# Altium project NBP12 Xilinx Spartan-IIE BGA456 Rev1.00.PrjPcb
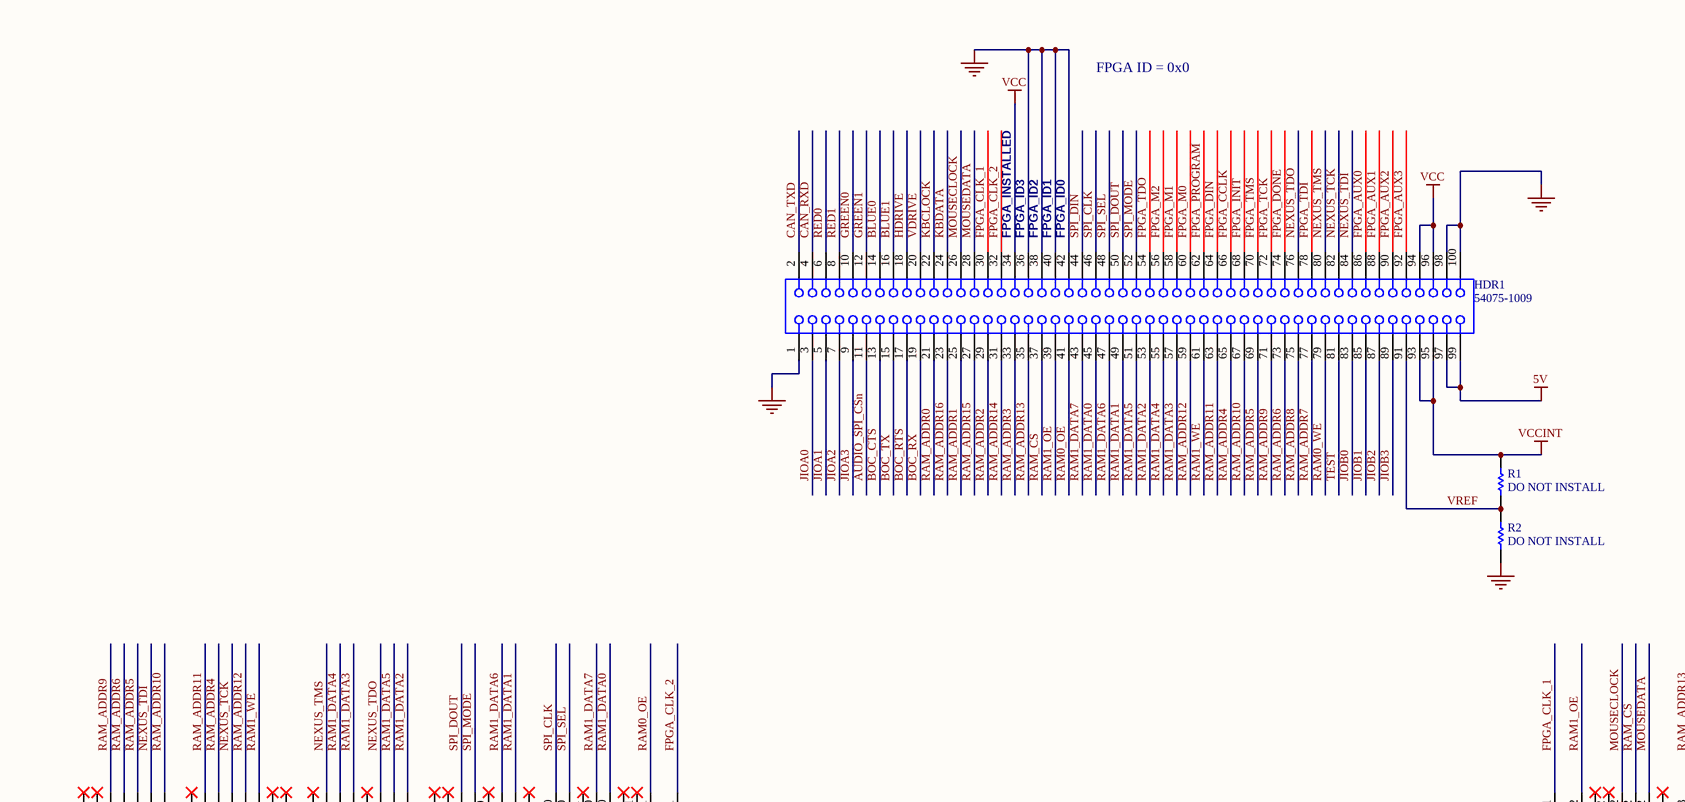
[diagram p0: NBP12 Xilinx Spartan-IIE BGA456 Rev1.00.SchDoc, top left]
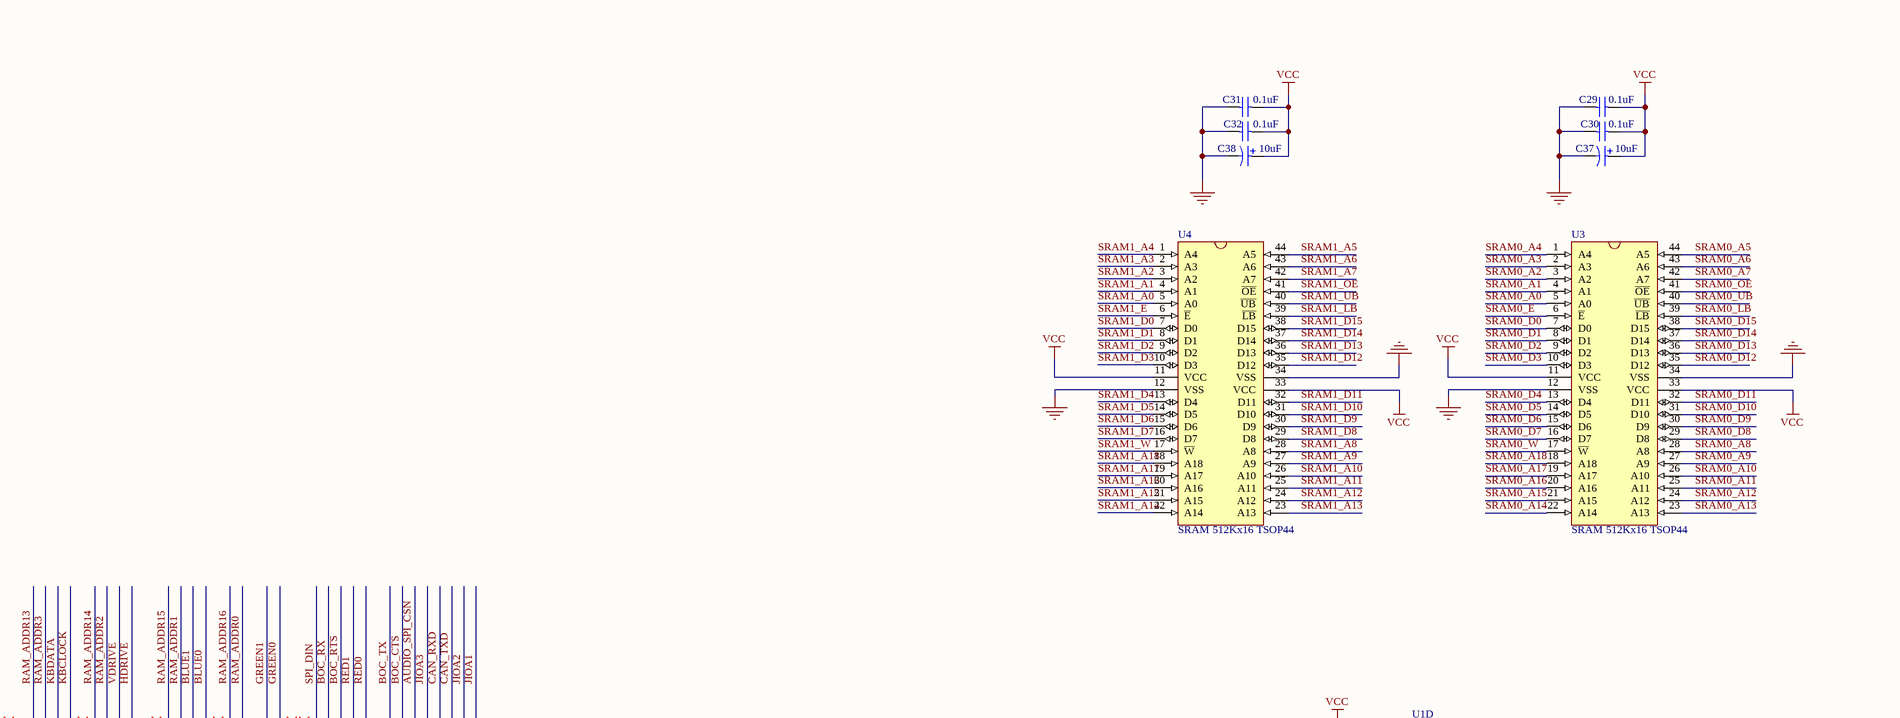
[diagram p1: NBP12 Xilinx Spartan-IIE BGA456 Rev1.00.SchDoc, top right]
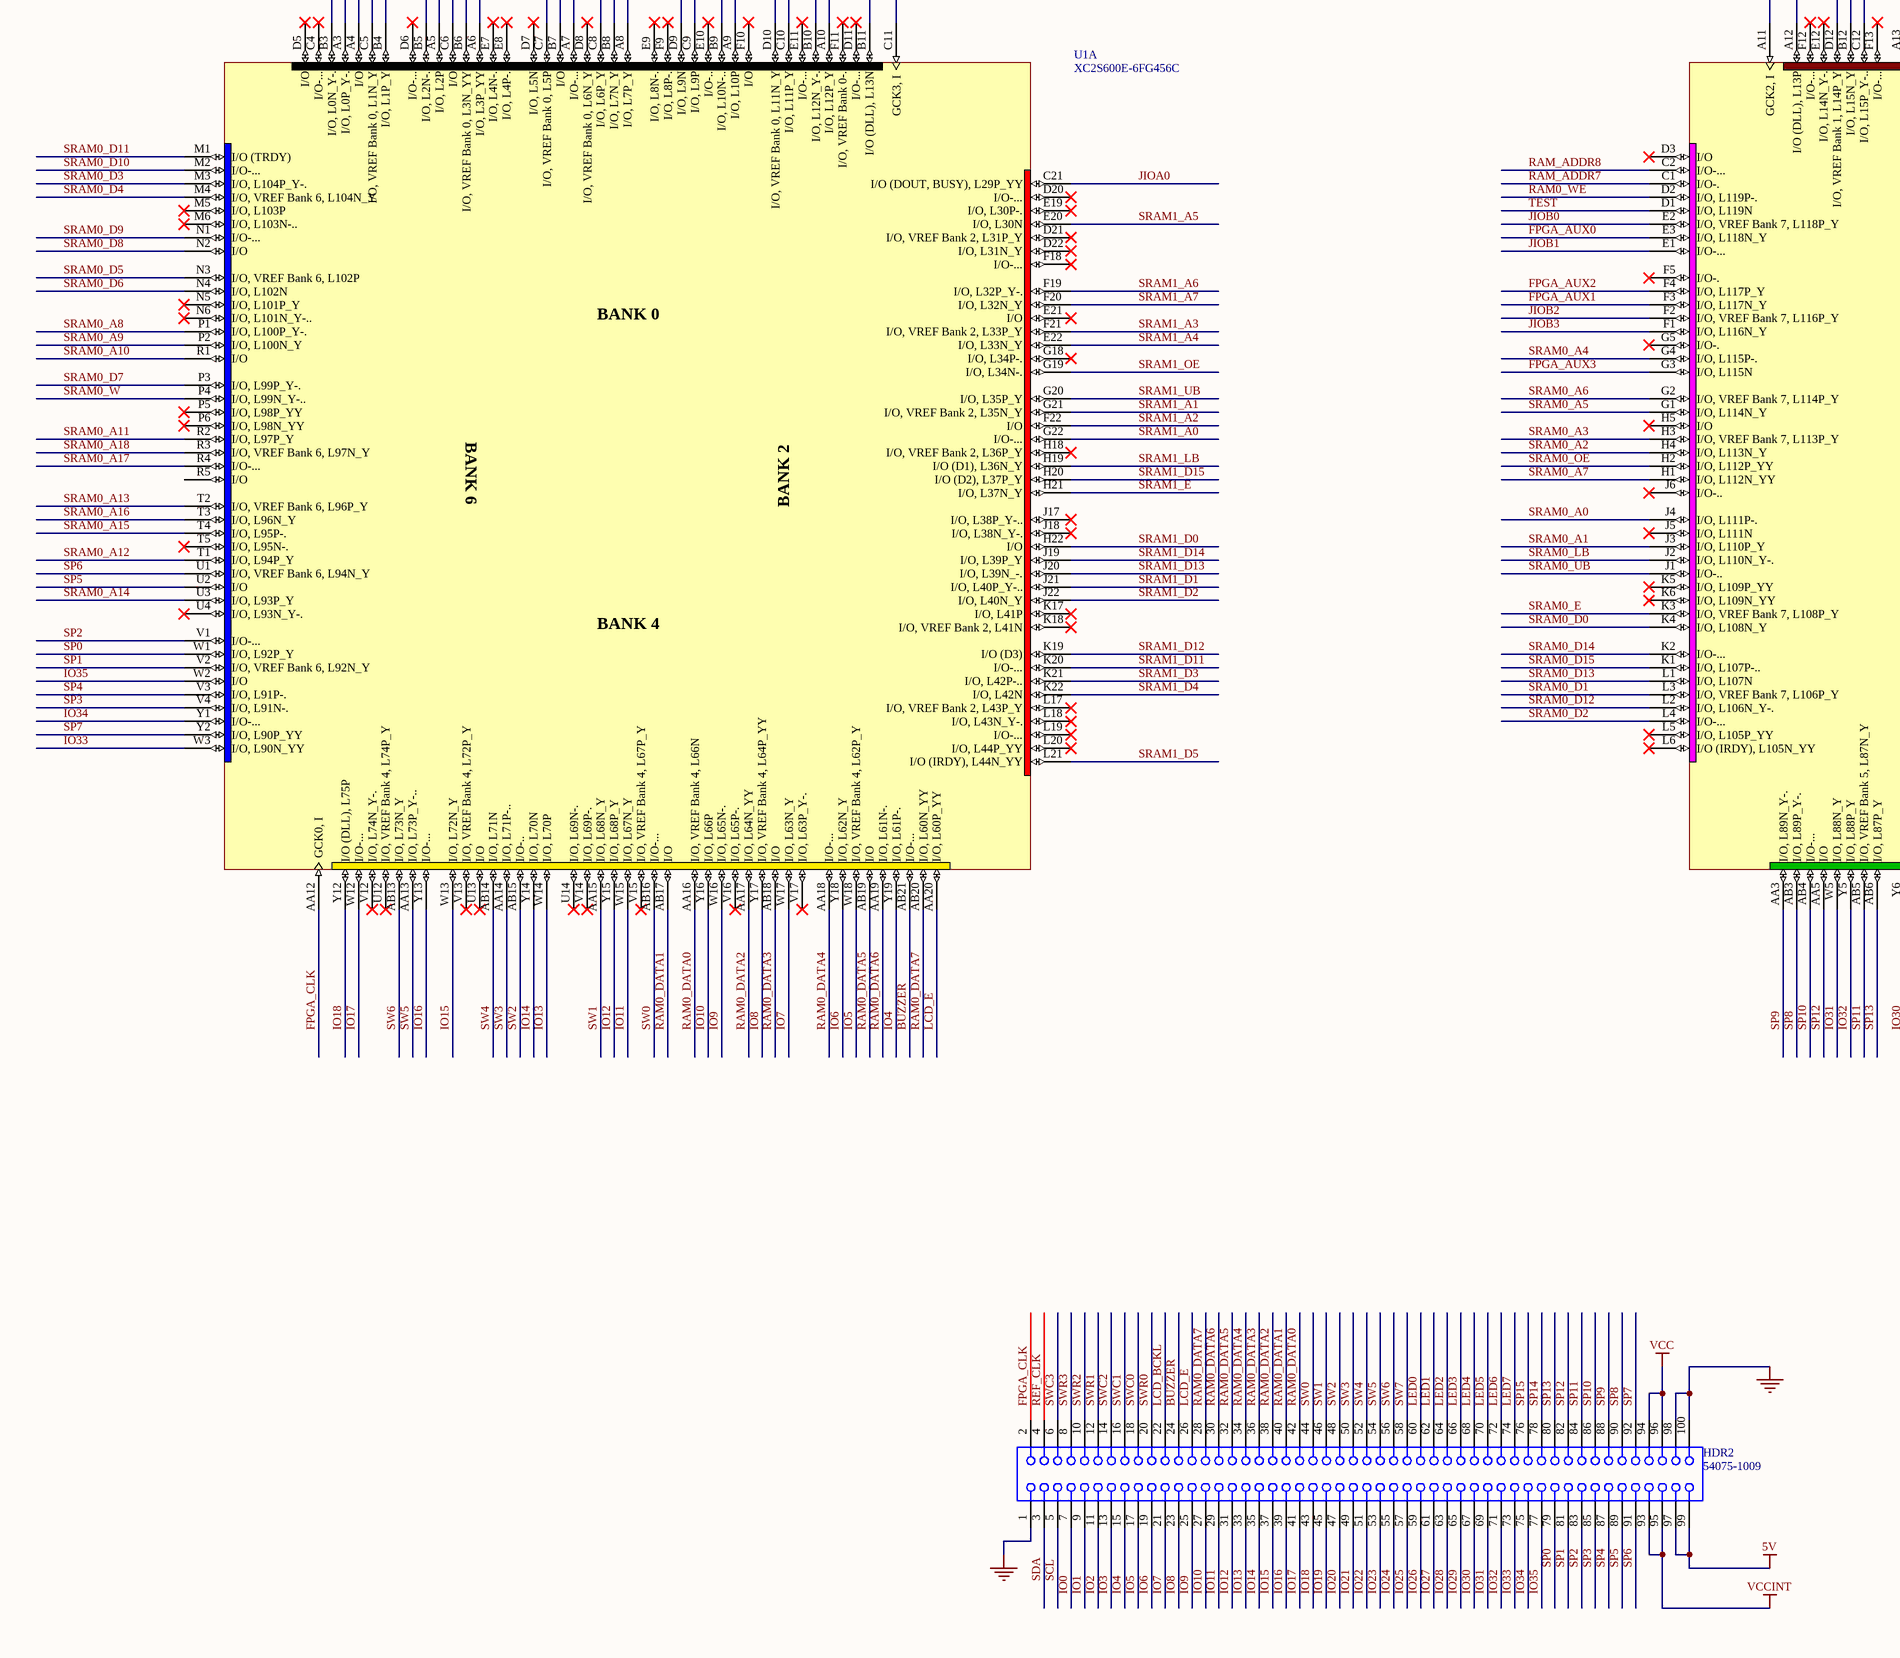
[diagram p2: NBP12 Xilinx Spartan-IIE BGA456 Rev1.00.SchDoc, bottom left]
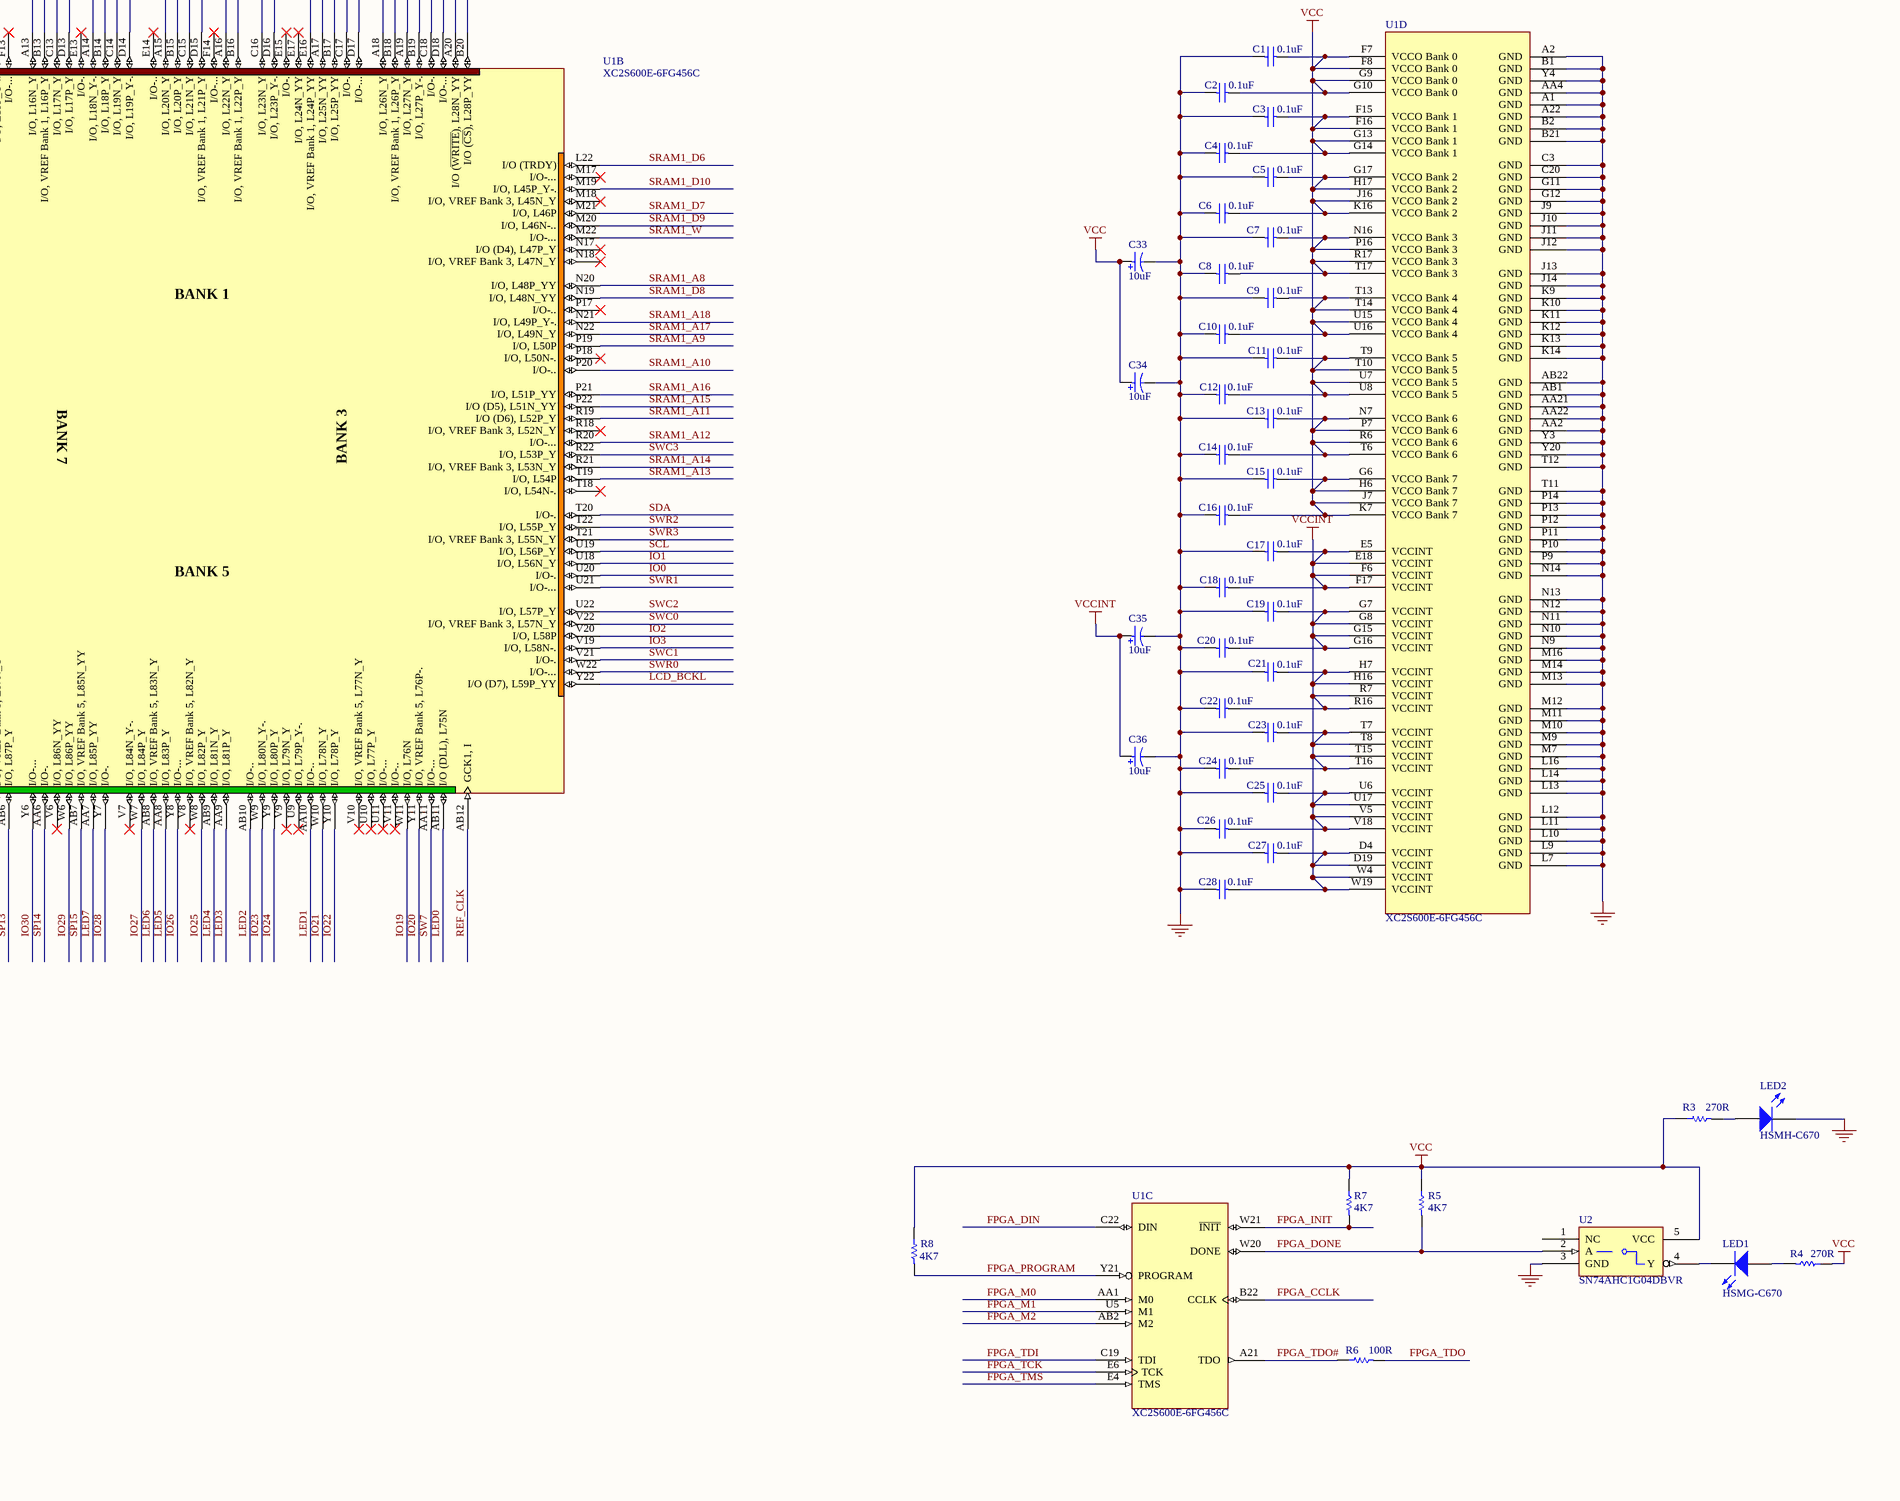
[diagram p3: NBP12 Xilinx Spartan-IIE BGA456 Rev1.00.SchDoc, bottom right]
1 sheet, 54 parts. Net scope: global (net labels, ports and power ports of the same name join across sheets).
Board file: NBP12 Xilinx Spartan-IIE BGA456 Rev1.00.PcbDoc

## Sheet NBP12 Xilinx Spartan-IIE BGA456 Rev1.00.SchDoc
size D; Organization: Altium Limited; Address1: L3, 12a Rodborough Rd; Address2: Frenchs Forest; Address3: NSW; Address4: Australia 2086; DocumentNumber: 1; SheetNumber: 1; SheetTotal: 1

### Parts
C1  0.1uF  [CC1608-0603]
C2  0.1uF  [CC1608-0603]
C3  0.1uF  [CC1608-0603]
C4  0.1uF  [CC1608-0603]
C5  0.1uF  [CC1608-0603]
C6  0.1uF  [CC1608-0603]
C7  0.1uF  [CC1608-0603]
C8  0.1uF  [CC1608-0603]
C9  0.1uF  [CC1608-0603]
C10  0.1uF  [CC1608-0603]
C11  0.1uF  [CC1608-0603]
C12  0.1uF  [CC1608-0603]
C13  0.1uF  [CC1608-0603]
C14  0.1uF  [CC1608-0603]
C15  0.1uF  [CC1608-0603]
C16  0.1uF  [CC1608-0603]
C17  0.1uF  [CC1608-0603]
C18  0.1uF  [CC1608-0603]
C19  0.1uF  [CC1608-0603]
C20  0.1uF  [CC1608-0603]
C21  0.1uF  [CC1608-0603]
C22  0.1uF  [CC1608-0603]
C23  0.1uF  [CC1608-0603]
C24  0.1uF  [CC1608-0603]
C25  0.1uF  [CC1608-0603]
C26  0.1uF  [CC1608-0603]
C27  0.1uF  [CC1608-0603]
C28  0.1uF  [CC1608-0603]
C29  0.1uF  [CC1608-0603]
C30  0.1uF  [CC1608-0603]
C31  0.1uF  [CC1608-0603]
C32  0.1uF  [CC1608-0603]
C33  10uF  [MCCT-B]
C34  10uF  [MCCT-B]
C35  10uF  [MCCT-B]
C36  10uF  [MCCT-B]
C37  10uF  [MCCT-B]
C38  10uF  [MCCT-B]
HDR1  54075-1009  [54075]
HDR2  54075-1009  [54075]
LED1  HSMG-C670  [SMD _LED]
LED2  HSMH-C670  [SMD _LED]
R1  DO NOT INSTALL  [CC2012-0805]
R2  DO NOT INSTALL  [CC2012-0805]
R3  270R  [CC2012-0805]
R4  270R  [CC2012-0805]
R5  4K7  [CC2012-0805]
R6  100R  [CC2012-0805]
R7  4K7  [CC2012-0805]
R8  4K7  [CC2012-0805]
U1  XC2S600E-6FG456C  [FG456]  (parts A,B,C,D of 4)
U2  SN74AHC1G04DBVR  [SO-G5/P.95]
U3  SRAM 512Kx16 TSOP44  [SO-G44/P.8]
U4  SRAM 512Kx16 TSOP44  [SO-G44/P.8]

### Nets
5V: HDR1.97 HDR1.99 HDR2.97 HDR2.99
GND: C1.1 C2.1 C3.1 C4.1 C5.1 C6.1 C7.1 C8.1 C9.1 C10.1 C11.1 C12.1 C13.1 C14.1 C15.1 C16.1 C17.1 C18.1 C19.1 C20.1 C21.1 C22.1 C23.1 C24.1 C25.1 C26.1 C27.1 C28.1 C29.1 C30.1 C31.1 C32.1 C33.2 C34.2 C35.2 C36.2 C37.2 C38.2 HDR1.1 HDR1.36 HDR1.38 HDR1.40 HDR1.42 HDR1.98 HDR1.100 HDR2.1 HDR2.98 HDR2.100 LED2.2(K) R2.2 U1.A1(GND) U1.A2(GND) U1.A22(GND) U1.AA2(GND) U1.AA4(GND) U1.AA21(GND) U1.AA22(GND) U1.AB1(GND) U1.AB22(GND) U1.B1(GND) U1.B2(GND) U1.B21(GND) U1.C3(GND) U1.C20(GND) U1.G11(GND) U1.G12(GND) U1.J9(GND) U1.J10(GND) U1.J11(GND) U1.J12(GND) U1.J13(GND) U1.J14(GND) U1.K9(GND) U1.K10(GND) U1.K11(GND) U1.K12(GND) U1.K13(GND) U1.K14(GND) U1.L7(GND) U1.L9(GND) U1.L10(GND) U1.L11(GND) U1.L12(GND) U1.L13(GND) U1.L14(GND) U1.L16(GND) U1.M7(GND) U1.M9(GND) U1.M10(GND) U1.M11(GND) U1.M12(GND) U1.M13(GND) U1.M14(GND) U1.M16(GND) U1.N9(GND) U1.N10(GND) U1.N11(GND) U1.N12(GND) U1.N13(GND) U1.N14(GND) U1.P9(GND) U1.P10(GND) U1.P11(GND) U1.P12(GND) U1.P13(GND) U1.P14(GND) U1.T11(GND) U1.T12(GND) U1.Y3(GND) U1.Y4(GND) U1.Y20(GND) U2.3(GND) U3.12(VSS) U3.34(VSS) U4.12(VSS) U4.34(VSS)
VCC: C1.2 C2.2 C3.2 C4.2 C5.2 C6.2 C7.2 C8.2 C9.2 C10.2 C11.2 C12.2 C13.2 C14.2 C15.2 C16.2 C29.2 C30.2 C31.2 C32.2 C33.1 C34.1 C37.1 C38.1 HDR1.34 HDR1.94 HDR1.96 HDR2.94 HDR2.96 R3.1 R4.1 R5.1 R7.1 R8.1 U1.F7(VCCO_Bank_0) U1.F8(VCCO_Bank_0) U1.F15(VCCO_Bank_1) U1.F16(VCCO_Bank_1) U1.G6(VCCO_Bank_7) U1.G9(VCCO_Bank_0) U1.G10(VCCO_Bank_0) U1.G13(VCCO_Bank_1) U1.G14(VCCO_Bank_1) U1.G17(VCCO_Bank_2) U1.H6(VCCO_Bank_7) U1.H17(VCCO_Bank_2) U1.J7(VCCO_Bank_7) U1.J16(VCCO_Bank_2) U1.K7(VCCO_Bank_7) U1.K16(VCCO_Bank_2) U1.N7(VCCO_Bank_6) U1.N16(VCCO_Bank_3) U1.P7(VCCO_Bank_6) U1.P16(VCCO_Bank_3) U1.R6(VCCO_Bank_6) U1.R17(VCCO_Bank_3) U1.T6(VCCO_Bank_6) U1.T9(VCCO_Bank_5) U1.T10(VCCO_Bank_5) U1.T13(VCCO_Bank_4) U1.T14(VCCO_Bank_4) U1.T17(VCCO_Bank_3) U1.U7(VCCO_Bank_5) U1.U8(VCCO_Bank_5) U1.U15(VCCO_Bank_4) U1.U16(VCCO_Bank_4) U2.5(VCC) U3.11(VCC) U3.33(VCC) U4.11(VCC) U4.33(VCC)
VCCINT: C17.2 C18.2 C19.2 C20.2 C21.2 C22.2 C23.2 C24.2 C25.2 C26.2 C27.2 C28.2 C35.1 C36.1 HDR1.93 HDR1.95 HDR2.93 HDR2.95 R1.1 U1.D4(VCCINT) U1.D19(VCCINT) U1.E5(VCCINT) U1.E18(VCCINT) U1.F6(VCCINT) U1.F17(VCCINT) U1.G7(VCCINT) U1.G8(VCCINT) U1.G15(VCCINT) U1.G16(VCCINT) U1.H7(VCCINT) U1.H16(VCCINT) U1.R7(VCCINT) U1.R16(VCCINT) U1.T7(VCCINT) U1.T8(VCCINT) U1.T15(VCCINT) U1.T16(VCCINT) U1.U6(VCCINT) U1.U17(VCCINT) U1.V5(VCCINT) U1.V18(VCCINT) U1.W4(VCCINT) U1.W19(VCCINT)
AUDIO_SPI_CSn: HDR1.11 U1.A19(I/O,_L27N_Y)
BLUE0: HDR1.14 U1.D15(I/O,_VREF_Bank_1,_L21P_Y)
BLUE1: HDR1.16 U1.C15(I/O,_L21N_Y)
BOC_CTS: HDR1.13 U1.B18(I/O,_VREF_Bank_1,_L26P_Y)
BOC_RTS: HDR1.17 U1.B17(I/O,_L25P_YY)
BOC_RX: HDR1.19 U1.A17(I/O,_L25N_YY)
BOC_TX: HDR1.15 U1.A18(I/O,_L26N_Y)
BUZZER: HDR2.24 U1.AB21(I/O-...)
CAN_RXD: HDR1.4 U1.C18(I/O-.)
CAN_TXD: HDR1.2 U1.D18(I/O-...)
FPGA_AUX0: HDR1.86 U1.E3(I/O,_L118N_Y)
FPGA_AUX1: HDR1.88 U1.F3(I/O,_L117N_Y)
FPGA_AUX2: HDR1.90 U1.F4(I/O,_L117P_Y)
FPGA_AUX3: HDR1.92 U1.G3(I/O,_L115N)
FPGA_CCLK: HDR1.66 U1.B22(CCLK)
FPGA_CLK: HDR2.2 U1.AA12(GCK0,_I)
FPGA_CLK_1: HDR1.30 U1.A11(GCK2,_I)
FPGA_CLK_2: HDR1.32 U1.C11(GCK3,_I)
FPGA_DIN: HDR1.64 U1.C22(DIN)
FPGA_DONE: HDR1.74 R5.2 U1.W20(DONE) U2.2(A)
FPGA_INIT: HDR1.68 R7.2 U1.W21(~{INIT})
FPGA_M0: HDR1.60 U1.AA1(M0)
FPGA_M1: HDR1.58 U1.U5(M1)
FPGA_M2: HDR1.56 U1.AB2(M2)
FPGA_PROGRAM: HDR1.62 R8.2 U1.Y21(PROGRAM)
FPGA_TCK: HDR1.72 U1.E6(TCK)
FPGA_TDI: HDR1.78 U1.C19(TDI)
FPGA_TDO: HDR1.54 R6.2
FPGA_TDO#: R6.1 U1.A21(TDO)
FPGA_TMS: HDR1.70 U1.E4(TMS)
GREEN0: HDR1.10 U1.D16(I/O,_L23P_Y-.)
GREEN1: HDR1.12 U1.C16(I/O,_L23N_Y)
HDRIVE: HDR1.18 U1.D14(I/O,_L19P_Y-.)
IO0: HDR2.7 U1.U20(I/O-.)
IO1: HDR2.9 U1.U18(I/O,_L56N_Y)
IO2: HDR2.11 U1.V20(I/O,_L58P)
IO3: HDR2.13 U1.V19(I/O,_L58N-.)
IO4: HDR2.15 U1.Y19(I/O,_L61P-.)
IO5: HDR2.17 U1.W18(I/O,_VREF_Bank_4,_L62P_Y)
IO6: HDR2.19 U1.Y18(I/O,_L62N_Y)
IO7: HDR2.21 U1.W17(I/O,_L63N_Y)
IO8: HDR2.23 U1.Y17(I/O,_VREF_Bank_4,_L64P_YY)
IO9: HDR2.25 U1.W16(I/O,_L65N-.)
IO10: HDR2.27 U1.Y16(I/O,_L66P)
IO11: HDR2.29 U1.W15(I/O,_L67N_Y)
IO12: HDR2.31 U1.Y15(I/O,_L68P_Y)
IO13: HDR2.33 U1.W14(I/O,_L70P)
IO14: HDR2.35 U1.Y14(I/O,_L70N)
IO15: HDR2.37 U1.W13(I/O,_L72N_Y)
IO16: HDR2.39 U1.Y13(I/O-...)
IO17: HDR2.41 U1.W12(I/O-...)
IO18: HDR2.43 U1.Y12(I/O_(DLL),_L75P)
IO19: HDR2.45 U1.W11(I/O,_L76N)
IO20: HDR2.47 U1.Y11(I/O,_VREF_Bank_5,_L76P-.)
IO21: HDR2.49 U1.W10(I/O,_L78N_Y)
IO22: HDR2.51 U1.Y10(I/O,_L78P_Y)
IO23: HDR2.53 U1.W9(I/O,_L80N_Y-.)
IO24: HDR2.55 U1.Y9(I/O,_L80P_Y)
IO25: HDR2.57 U1.W8(I/O,_L82P_Y)
IO26: HDR2.59 U1.Y8(I/O-...)
IO27: HDR2.61 U1.W7(I/O,_L84P_Y)
IO28: HDR2.63 U1.Y7(I/O-.)
IO29: HDR2.65 U1.W6(I/O,_L86P_YY)
IO30: HDR2.67 U1.Y6(I/O-...)
IO31: HDR2.69 U1.W5(I/O,_L88N_Y)
IO32: HDR2.71 U1.Y5(I/O,_L88P_Y)
IO33: HDR2.73 U1.W3(I/O,_L90N_YY)
IO34: HDR2.75 U1.Y1(I/O-...)
IO35: HDR2.77 U1.W2(I/O)
JIOA0: HDR1.3 U1.C21(I/O_(DOUT,_BUSY),_L29P_YY)
JIOA1: HDR1.5 U1.B20(I/O_(~{CS}),_L28P_YY)
JIOA2: HDR1.7 U1.A20(I/O_(~{WRITE}),_L28N_YY)
JIOA3: HDR1.9 U1.B19(I/O,_L27P_Y-.)
JIOB0: HDR1.83 U1.E2(I/O,_VREF_Bank_7,_L118P_Y)
JIOB1: HDR1.85 U1.E1(I/O-...)
JIOB2: HDR1.87 U1.F2(I/O,_VREF_Bank_7,_L116P_Y)
JIOB3: HDR1.89 U1.F1(I/O,_L116N_Y)
KBCLOCK: HDR1.22 U1.D13(I/O,_L17P_Y)
KBDATA: HDR1.24 U1.C13(I/O,_L17N_Y)
LCD_BCKL: HDR2.22 U1.Y22(I/O_(D7),_L59P_YY)
LCD_E: HDR2.26 U1.AA20(I/O,_L60P_YY)
LED0: HDR2.60 U1.AB11(I/O_(DLL),_L75N)
LED1: HDR2.62 U1.AA10(I/O-..)
LED2: HDR2.64 U1.AB10(I/O-..)
LED3: HDR2.66 U1.AA9(I/O,_L81P_Y)
LED4: HDR2.68 U1.AB9(I/O,_L81N_Y)
LED5: HDR2.70 U1.AA8(I/O,_L83P_Y)
LED6: HDR2.72 U1.AB8(I/O,_VREF_Bank_5,_L83N_Y)
LED7: HDR2.74 U1.AA7(I/O,_L85P_YY)
MOUSECLOCK: HDR1.26 U1.D12(I/O,_VREF_Bank_1,_L14P_Y)
MOUSEDATA: HDR1.28 U1.C12(I/O,_L15P_Y-..)
NEXUS_TCK: HDR1.82 U1.C6(I/O)
NEXUS_TDI: HDR1.84 U1.C5(I/O,_VREF_Bank_0,_L1N_Y)
NEXUS_TDO: HDR1.76 U1.C8(I/O,_L6P_Y)
NEXUS_TMS: HDR1.80 U1.C7(I/O,_VREF_Bank_0,_L5P)
RAM0_DATA0: HDR2.42 U1.AA16(I/O,_VREF_Bank_4,_L66N)
RAM0_DATA1: HDR2.40 U1.AB17(I/O)
RAM0_DATA2: HDR2.38 U1.AA17(I/O,_L64N_YY)
RAM0_DATA3: HDR2.36 U1.AB18(I/O)
RAM0_DATA4: HDR2.34 U1.AA18(I/O-...)
RAM0_DATA5: HDR2.32 U1.AB19(I/O)
RAM0_DATA6: HDR2.30 U1.AA19(I/O,_L61N-.)
RAM0_DATA7: HDR2.28 U1.AB20(I/O,_L60N_YY)
RAM0_OE: HDR1.41 U1.B11(I/O_(DLL),_L13N)
RAM0_WE: HDR1.79 U1.D2(I/O,_L119P-.)
RAM1_DATA0: HDR1.45 U1.A10(I/O,_L12P_Y)
RAM1_DATA1: HDR1.49 U1.A9(I/O,_L10P)
RAM1_DATA2: HDR1.53 U1.A8(I/O,_L7P_Y)
RAM1_DATA3: HDR1.57 U1.A7(I/O-...)
RAM1_DATA4: HDR1.55 U1.B7(I/O)
RAM1_DATA5: HDR1.51 U1.B8(I/O,_L7N_Y)
RAM1_DATA6: HDR1.47 U1.B9(I/O,_L10N-..)
RAM1_DATA7: HDR1.43 U1.B10(I/O,_L12N_Y-.)
RAM1_OE: HDR1.39 U1.A12(I/O_(DLL),_L13P)
RAM1_WE: HDR1.61 U1.A6(I/O,_L3P_YY)
RAM_ADDR0: HDR1.21 U1.B16(I/O,_VREF_Bank_1,_L22P_Y)
RAM_ADDR1: HDR1.25 U1.B15(I/O,_L20P_Y)
RAM_ADDR2: HDR1.29 U1.B14(I/O,_L18P_Y)
RAM_ADDR3: HDR1.33 U1.B13(I/O,_VREF_Bank_1,_L16P_Y)
RAM_ADDR4: HDR1.65 U1.A5(I/O,_L2P)
RAM_ADDR5: HDR1.69 U1.A4(I/O)
RAM_ADDR6: HDR1.73 U1.A3(I/O,_L0P_Y-.)
RAM_ADDR7: HDR1.77 U1.C1(I/O-.)
RAM_ADDR8: HDR1.75 U1.C2(I/O-...)
RAM_ADDR9: HDR1.71 U1.B3(I/O,_L0N_Y-.)
RAM_ADDR10: HDR1.67 U1.B4(I/O,_L1P_Y)
RAM_ADDR11: HDR1.63 U1.B5(I/O,_L2N-.)
RAM_ADDR12: HDR1.59 U1.B6(I/O,_VREF_Bank_0,_L3N_YY)
RAM_ADDR13: HDR1.35 U1.A13(I/O,_L16N_Y)
RAM_ADDR14: HDR1.31 U1.A14(I/O,_L18N_Y-.)
RAM_ADDR15: HDR1.27 U1.A15(I/O,_L20N_Y)
RAM_ADDR16: HDR1.23 U1.A16(I/O,_L22N_Y)
RAM_CS: HDR1.37 U1.B12(I/O,_L15N_Y)
RED0: HDR1.6 U1.D17(I/O-...)
RED1: HDR1.8 U1.C17(I/O-.)
REF_CLK: HDR2.4 U1.AB12(GCK1,_I)
SCL: HDR2.5 U1.U19(I/O,_L56P_Y)
SDA: HDR2.3 U1.T20(I/O-.)
SP0: HDR2.79 U1.W1(I/O,_L92P_Y)
SP1: HDR2.81 U1.V2(I/O,_VREF_Bank_6,_L92N_Y)
SP2: HDR2.83 U1.V1(I/O-...)
SP3: HDR2.85 U1.V4(I/O,_L91N-.)
SP4: HDR2.87 U1.V3(I/O,_L91P-.)
SP5: HDR2.89 U1.U2(I/O)
SP6: HDR2.91 U1.U1(I/O,_VREF_Bank_6,_L94N_Y)
SP7: HDR2.92 U1.Y2(I/O,_L90P_YY)
SP8: HDR2.90 U1.AB3(I/O,_L89P_Y-.)
SP9: HDR2.88 U1.AA3(I/O,_L89N_Y-.)
SP10: HDR2.86 U1.AB4(I/O-...)
SP11: HDR2.84 U1.AB5(I/O,_VREF_Bank_5,_L87N_Y)
SP12: HDR2.82 U1.AA5(I/O)
SP13: HDR2.80 U1.AB6(I/O,_L87P_Y)
SP14: HDR2.78 U1.AA6(I/O-.)
SP15: HDR2.76 U1.AB7(I/O,_VREF_Bank_5,_L85N_YY)
SPI_CLK: HDR1.46 U1.D10(I/O,_VREF_Bank_0,_L11N_Y)
SPI_DIN: HDR1.44 U1.E16(I/O,_VREF_Bank_1,_L24P_YY)
SPI_DOUT: HDR1.50 U1.D9(I/O,_L9N)
SPI_MODE: HDR1.52 U1.C9(I/O,_L9P)
SPI_SEL: HDR1.48 U1.C10(I/O,_L11P_Y)
SRAM0_A0: U1.J4(I/O,_L111P-.) U3.5(A0)
SRAM0_A1: U1.J3(I/O,_L110P_Y) U3.4(A1)
SRAM0_A2: U1.H4(I/O,_L113N_Y) U3.3(A2)
SRAM0_A3: U1.H3(I/O,_VREF_Bank_7,_L113P_Y) U3.2(A3)
SRAM0_A4: U1.G4(I/O,_L115P-.) U3.1(A4)
SRAM0_A5: U1.G1(I/O,_L114N_Y) U3.44(A5)
SRAM0_A6: U1.G2(I/O,_VREF_Bank_7,_L114P_Y) U3.43(A6)
SRAM0_A7: U1.H1(I/O,_L112N_YY) U3.42(A7)
SRAM0_A8: U1.P1(I/O,_L100P_Y-.) U3.28(A8)
SRAM0_A9: U1.P2(I/O,_L100N_Y) U3.27(A9)
SRAM0_A10: U1.R1(I/O) U3.26(A10)
SRAM0_A11: U1.R2(I/O,_L97P_Y) U3.25(A11)
SRAM0_A12: U1.T1(I/O,_L94P_Y) U3.24(A12)
SRAM0_A13: U1.T2(I/O,_VREF_Bank_6,_L96P_Y) U3.23(A13)
SRAM0_A14: U1.U3(I/O,_L93P_Y) U3.22(A14)
SRAM0_A15: U1.T4(I/O,_L95P-.) U3.21(A15)
SRAM0_A16: U1.T3(I/O,_L96N_Y) U3.20(A16)
SRAM0_A17: U1.R4(I/O-...) U3.19(A17)
SRAM0_A18: U1.R3(I/O,_VREF_Bank_6,_L97N_Y) U3.18(A18)
SRAM0_D0: U1.K4(I/O,_L108N_Y) U3.7(D0)
SRAM0_D1: U1.L3(I/O,_VREF_Bank_7,_L106P_Y) U3.8(D1)
SRAM0_D2: U1.L4(I/O-...) U3.9(D2)
SRAM0_D3: U1.M3(I/O,_L104P_Y-.) U3.10(D3)
SRAM0_D4: U1.M4(I/O,_VREF_Bank_6,_L104N_Y) U3.13(D4)
SRAM0_D5: U1.N3(I/O,_VREF_Bank_6,_L102P) U3.14(D5)
SRAM0_D6: U1.N4(I/O,_L102N) U3.15(D6)
SRAM0_D7: U1.P3(I/O,_L99P_Y-.) U3.16(D7)
SRAM0_D8: U1.N2(I/O) U3.29(D8)
SRAM0_D9: U1.N1(I/O-...) U3.30(D9)
SRAM0_D10: U1.M2(I/O-...) U3.31(D10)
SRAM0_D11: U1.M1(I/O_(TRDY)) U3.32(D11)
SRAM0_D12: U1.L2(I/O,_L106N_Y-.) U3.35(D12)
SRAM0_D13: U1.L1(I/O,_L107N) U3.36(D13)
SRAM0_D14: U1.K2(I/O-...) U3.37(D14)
SRAM0_D15: U1.K1(I/O,_L107P-..) U3.38(D15)
SRAM0_E: U1.K3(I/O,_VREF_Bank_7,_L108P_Y) U3.6(~{E})
SRAM0_LB: U1.J2(I/O,_L110N_Y-.) U3.39(~{LB})
SRAM0_OE: U1.H2(I/O,_L112P_YY) U3.41(~{OE})
SRAM0_UB: U1.J1(I/O-..) U3.40(~{UB})
SRAM0_W: U1.P4(I/O,_L99N_Y-..) U3.17(~{W})
SRAM1_A0: U1.G22(I/O-...) U4.5(A0)
SRAM1_A1: U1.G21(I/O,_VREF_Bank_2,_L35N_Y) U4.4(A1)
SRAM1_A2: U1.F22(I/O) U4.3(A2)
SRAM1_A3: U1.F21(I/O,_VREF_Bank_2,_L33P_Y) U4.2(A3)
SRAM1_A4: U1.E22(I/O,_L33N_Y) U4.1(A4)
SRAM1_A5: U1.E20(I/O,_L30N) U4.44(A5)
SRAM1_A6: U1.F19(I/O,_L32P_Y-.) U4.43(A6)
SRAM1_A7: U1.F20(I/O,_L32N_Y) U4.42(A7)
SRAM1_A8: U1.N20(I/O,_L48P_YY) U4.28(A8)
SRAM1_A9: U1.P19(I/O,_L50P) U4.27(A9)
SRAM1_A10: U1.P20(I/O-..) U4.26(A10)
SRAM1_A11: U1.R19(I/O_(D6),_L52P_Y) U4.25(A11)
SRAM1_A12: U1.R20(I/O-...) U4.24(A12)
SRAM1_A13: U1.T19(I/O,_L54P) U4.23(A13)
SRAM1_A14: U1.R21(I/O,_VREF_Bank_3,_L53N_Y) U4.22(A14)
SRAM1_A15: U1.P22(I/O_(D5),_L51N_YY) U4.21(A15)
SRAM1_A16: U1.P21(I/O,_L51P_YY) U4.20(A16)
SRAM1_A17: U1.N22(I/O,_L49N_Y) U4.19(A17)
SRAM1_A18: U1.N21(I/O,_L49P_Y-.) U4.18(A18)
SRAM1_D0: U1.H22(I/O) U4.7(D0)
SRAM1_D1: U1.J21(I/O,_L40P_Y-..) U4.8(D1)
SRAM1_D2: U1.J22(I/O,_L40N_Y) U4.9(D2)
SRAM1_D3: U1.K21(I/O,_L42P-..) U4.10(D3)
SRAM1_D4: U1.K22(I/O,_L42N) U4.13(D4)
SRAM1_D5: U1.L21(I/O_(IRDY),_L44N_YY) U4.14(D5)
SRAM1_D6: U1.L22(I/O_(TRDY)) U4.15(D6)
SRAM1_D7: U1.M21(I/O,_L46P) U4.16(D7)
SRAM1_D8: U1.N19(I/O,_L48N_YY) U4.29(D8)
SRAM1_D9: U1.M20(I/O,_L46N-..) U4.30(D9)
SRAM1_D10: U1.M19(I/O,_L45P_Y-.) U4.31(D10)
SRAM1_D11: U1.K20(I/O-...) U4.32(D11)
SRAM1_D12: U1.K19(I/O_(D3)) U4.35(D12)
SRAM1_D13: U1.J20(I/O,_L39N_-.) U4.36(D13)
SRAM1_D14: U1.J19(I/O,_L39P_Y) U4.37(D14)
SRAM1_D15: U1.H20(I/O_(D2),_L37P_Y) U4.38(D15)
SRAM1_E: U1.H21(I/O,_L37N_Y) U4.6(~{E})
SRAM1_LB: U1.H19(I/O_(D1),_L36N_Y) U4.39(~{LB})
SRAM1_OE: U1.G19(I/O,_L34N-.) U4.41(~{OE})
SRAM1_UB: U1.G20(I/O,_L35P_Y) U4.40(~{UB})
SRAM1_W: U1.M22(I/O-...) U4.17(~{W})
SW0: HDR2.44 U1.AB16(I/O-...)
SW1: HDR2.46 U1.AA15(I/O,_L68N_Y)
SW2: HDR2.48 U1.AB15(I/O-..)
SW3: HDR2.50 U1.AA14(I/O,_L71P-..)
SW4: HDR2.52 U1.AB14(I/O,_L71N)
SW5: HDR2.54 U1.AA13(I/O,_L73P_Y-..)
SW6: HDR2.56 U1.AB13(I/O,_L73N_Y)
SW7: HDR2.58 U1.AA11(I/O-...)
SWC0: HDR2.18 U1.V22(I/O,_VREF_Bank_3,_L57N_Y)
SWC1: HDR2.16 U1.V21(I/O-.)
SWC2: HDR2.14 U1.U22(I/O,_L57P_Y)
SWC3: HDR2.6 U1.R22(I/O,_L53P_Y)
SWR0: HDR2.20 U1.W22(I/O-...)
SWR1: HDR2.12 U1.U21(I/O-...)
SWR2: HDR2.10 U1.T22(I/O,_L55P_Y)
SWR3: HDR2.8 U1.T21(I/O,_VREF_Bank_3,_L55N_Y)
TEST: HDR1.81 U1.D1(I/O,_L119N)
VDRIVE: HDR1.20 U1.C14(I/O,_L19N_Y)
VREF: HDR1.91 R1.2 R2.1
NetLED1_1: LED1.1(A) R4.2
NetLED1_2: LED1.2(K) U2.4(Y)
NetLED2_1: LED2.1(A) R3.2

Not connected (* = marked no-connect by the designer): U1 C4(I/O-...)* D3(I/O)* D5(I/O)* D6(I/O-...)* D7(I/O,_L5N)* D8(I/O,_VREF_Bank_0,_L6N_Y)* D11(I/O-...)* D20(I/O-...)* D21(I/O,_VREF_Bank_2,_L31P_Y)* D22(I/O,_L31N_Y)* E7(I/O,_L4N-.)* E8(I/O,_L4P-.)* E9(I/O,_L8N-.)* E10(I/O-..)* E11(I/O-...)* E12(I/O,_L14N_Y-.)* E13(I/O-.)* E14(I/O-..)* E15(I/O-.)* E17(I/O,_L24N_YY)* E19(I/O,_L30P-.)* E21(I/O)* F5(I/O-.)* F9(I/O,_L8P-.)* F10(I/O)* F11(I/O,_VREF_Bank_0-.)* F12(I/O-...)* F13(I/O-...)* F14(I/O-...)* F18(I/O-...)* G5(I/O-.)* G18(I/O,_L34P-.)* H5(I/O)* H18(I/O,_VREF_Bank_2,_L36P_Y)* J5(I/O,_L111N)* J6(I/O-..)* J17(I/O,_L38P_Y-..)* J18(I/O,_L38N_Y-.)* K5(I/O,_L109P_YY)* K6(I/O,_L109N_YY)* K17(I/O,_L41P)* K18(I/O,_VREF_Bank_2,_L41N)* L5(I/O,_L105P_YY)* L6(I/O_(IRDY),_L105N_YY)* L17(I/O,_VREF_Bank_2,_L43P_Y)* L18(I/O,_L43N_Y-.)* L19(I/O-...)* L20(I/O,_L44P_YY)* M5(I/O,_L103P)* M6(I/O,_L103N-..)* M17(I/O-...)* M18(I/O,_VREF_Bank_3,_L45N_Y)* N5(I/O,_L101P_Y)* N6(I/O,_L101N_Y-..)* N17(I/O_(D4),_L47P_Y)* N18(I/O,_VREF_Bank_3,_L47N_Y)* P5(I/O,_L98P_YY)* P6(I/O,_L98N_YY)* P17(I/O-..)* P18(I/O,_L50N-.)* R5(I/O) R18(I/O,_VREF_Bank_3,_L52N_Y)* T5(I/O,_L95N-.)* T18(I/O,_L54N-.)* U4(I/O,_L93N_Y-.)* U9(I/O,_L79P_Y-.)* U10(I/O,_L77P_Y)* U11(I/O-...)* U12(I/O,_VREF_Bank_4,_L74P_Y)* U13(I/O)* U14(I/O,_L69N-.)* V6(I/O,_L86N_YY)* V7(I/O,_L84N_Y-.)* V8(I/O,_VREF_Bank_5,_L82N_Y)* V9(I/O,_L79N_Y)* V10(I/O,_VREF_Bank_5,_L77N_Y)* V11(I/O-..)* V12(I/O,_L74N_Y-.)* V13(I/O,_VREF_Bank_4,_L72P_Y)* V14(I/O,_L69P-.)* V15(I/O,_VREF_Bank_4,_L67P_Y)* V16(I/O,_L65P-.)* V17(I/O,_L63P_Y-.)*; U2 1(NC)

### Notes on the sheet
- FPGA ID = 0x0
- (near HDR1) FPGA_INSTALLED
- (near HDR1) FPGA_ID3
- (near HDR1) FPGA_ID2
- (near HDR1) FPGA_ID1
- (near HDR1) FPGA_ID0

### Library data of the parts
C1-C32 = CAP: Capacitor
C33-C38 = CAP_POLAR: Polar Capacitor
HDR1 HDR2 = 54075-1009: Board-to-Board, Docking Station, 0.80mm (.031") Pitch, Shielded Receptacle, Vertical, Ultra Low Profile, SMT; Manufacturer: Molex; Package Information: Latest Revision: Jun-2001; Mating Height: 8.5mm; Voltage: 100V; Current: 0.5A; Contact Resistance: 40mOhm max; PCB Layout: Complies with Manufacturer's Recommendation.
LED1 = HSMX-C670: GREEN AS AlGaAs SMD LED; Manufacturer: Agilent
LED2 = HSMX-C670: RED AS AlGaAs SMD LED; Manufacturer: Agilent
R1-R8 = RES: Resistor; Manufacturer: Phycomp
U1 = XC2S600E-6FG456C: Spartan-IIE 1.8V FPGA, 456-Ball FBGA, Standard Performance, Commercial Grade; Package Information: Latest Revision: ver1.1, Apr-2001; Code - JEDEC: MO-151-AAJ-1
U2 = SN74AHC1G04DBVR: Single Gate Inverter; Manufacturer: Texas Instruments
U3 U4 = SRAM 512Kx16 TSOP44: 512Kx16Bit SRAM TSOP44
